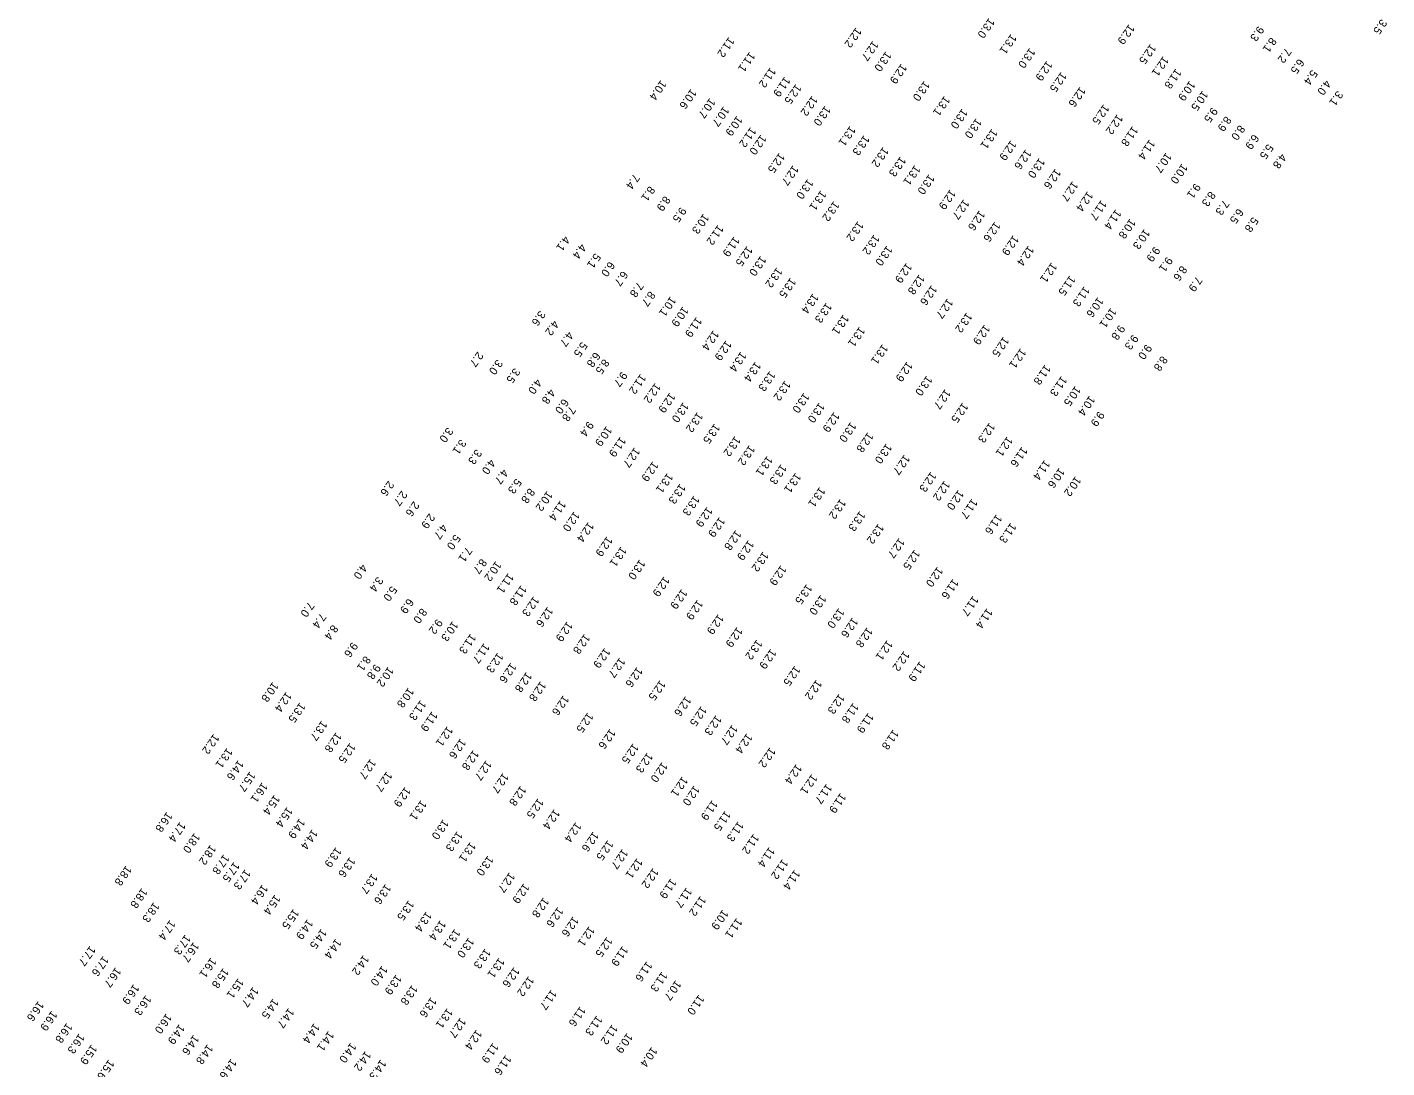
# Model space of a CAD drawing. Extents: x 815385 to 820851, y 582449 to 604245.
# Drawn here: x 818563 to 819412, y 587113 to 587763 of the extents above; entities that cross this region are included whole.
import ezdxf

# ---------------------------------------------------------------- set-up
doc = ezdxf.new("R2010")
doc.units = 0
doc.layers.add('V-TOPO-SOUN-021509', color=7, linetype='Continuous')

msp = doc.modelspace()

# ---------------------------------------------------------------- texts
at = {"layer": 'V-TOPO-SOUN-021509'}
for s, p in [('13.0 ', (819163.67, 587769.28)), ('3.5', (819408.79, 587768.65)), ('12.2 ', (819080.54, 587763.34)), ('12.9 ', (819251.12, 587765.37)), ('9.3', (819331.93, 587764.32)), ('11.2 ', (819001.1, 587757.36)), ('12.7 ', (819091.1, 587755.05)), ('13.1 ', (819177.41, 587759.3)), ('12.5 ', (819264.54, 587753.07)), ('8.1', (819339.75, 587757.22)), ('11.1 ', (819014.07, 587748.08)), ('13.0 ', (819099.21, 587748.44)), ('13.0 ', (819189.07, 587750.55)), ('12.1 ', (819272.52, 587745.38)), ('7.2', (819349.04, 587750.66)), ('6.5', (819357.13, 587743.9)), ('11.2 ', (819027.02, 587738.39)), ('12.9 ', (819108.87, 587740.75)), ('12.9 ', (819199.85, 587742.58)), ('12.5 ', (819208.76, 587735.56)), ('11.8 ', (819280.39, 587737.66)), ('5.4', (819365.43, 587736.98)), ('10.4 ', (818958.59, 587730.47)), ('11.9 ', (819036, 587732.64)), ('12.5 ', (819042.99, 587728.04)), ('13.0 ', (819123.2, 587729.98)), ('12.6 ', (819220.54, 587726.28)), ('10.9 ', (819289.01, 587730.06)), ('4.0', (819373.86, 587730.67)), ('10.6 ', (818977.42, 587725.03)), ('10.7 ', (818989.16, 587719.22)), ('12.2 ', (819053.14, 587720.69)), ('13.1 ', (819135.81, 587720.61)), ('10.5 ', (819297.1, 587723.93)), ('3.1', (819381.31, 587723.87)), ('10.7 ', (818997.84, 587714.08)), ('13.0 ', (819061.23, 587714.45)), ('13.0 ', (819146.88, 587712.65)), ('12.5 ', (819235.3, 587715.36)), ('12.2 ', (819243.84, 587709.12)), ('9.5', (819302.99, 587713.51)), ('10.9 ', (819006.15, 587708.19)), ('11.2 ', (819014.71, 587701.1)), ('13.1 ', (819076.81, 587701.82)), ('13.0 ', (819155.65, 587706.64)), ('11.8 ', (819253.37, 587701.71)), ('8.9', (819311.54, 587708)), ('8.0', (819320.07, 587702.48)), ('12.0 ', (819021.12, 587696.41)), ('13.3 ', (819085.55, 587696.06)), ('13.1 ', (819165.49, 587700.08)), ('12.9 ', (819177.26, 587692.87)), ('11.4 ', (819263.94, 587693.41)), ('6.9', (819328.83, 587696.71)), ('12.5 ', (819032.61, 587685.06)), ('13.2 ', (819097.49, 587688.67)), ('12.6 ', (819186.63, 587687.27)), ('10.7 ', (819274.33, 587685.21)), ('5.5', (819337.82, 587690.64)), ('4.8', (819346.06, 587684.73)), ('12.7 ', (819041.19, 587677.26)), ('13.3 ', (819108.26, 587682.75)), ('13.1 ', (819117.29, 587677.34)), ('13.0 ', (819195.11, 587681.87)), ('12.6 ', (819205.09, 587675.12)), ('10.0 ', (819284.26, 587678.31)), ('7.4', (818941.85, 587671.9)), ('13.0 ', (819050.41, 587668.74)), ('13.0 ', (819126.15, 587671.64)), ('12.7 ', (819215.88, 587667.34)), ('8.1', (818951.42, 587664.33)), ('8.9', (818961, 587658.18)), ('13.1 ', (819058.56, 587661.58)), ('12.9 ', (819139.4, 587662.18)), ('12.4 ', (819225.24, 587661)), ('9.1', (819292.35, 587666.1)), ('8.3', (819301.65, 587661.1)), ('9.5', (818970.97, 587651.19)), ('13.2 ', (819066.69, 587654.91)), ('12.7 ', (819147.83, 587656)), ('11.7 ', (819233.79, 587655.56)), ('11.4 ', (819242.84, 587649.74)), ('7.3', (819310.23, 587655.69)), ('6.5', (819319.14, 587650.38)), ('10.3 ', (818985.23, 587647.04)), ('13.2 ', (819081.77, 587642.33)), ('12.6 ', (819157.69, 587649.12)), ('12.6 ', (819167.32, 587642.06)), ('10.8 ', (819251.78, 587643.95)), ('5.8', (819328.44, 587645.05)), ('4.1', (818898.33, 587633.2)), ('11.2 ', (818994.33, 587640.06)), ('11.9 ', (819004.35, 587632.79)), ('13.2 ', (819091.82, 587633.97)), ('12.9 ', (819178.82, 587633.56)), ('10.3 ', (819260.73, 587637.47)), ('4.4', (818908.49, 587628.38)), ('12.5 ', (819012.46, 587626.8)), ('13.0 ', (819099.84, 587627.11)), ('12.4 ', (819188.26, 587627.02)), ('9.9', (819267.03, 587626.54)), ('5.1', (818917.54, 587622.42)), ('6.0', (818926.35, 587617.25)), ('13.0 ', (819020.98, 587620.7)), ('12.9 ', (819112.07, 587616.32)), ('12.1 ', (819202.72, 587616.52)), ('9.1', (819274.86, 587620.16)), ('6.7', (818934.53, 587611.35)), ('13.2 ', (819031.06, 587613.45)), ('13.5 ', (819039.57, 587607.03)), ('12.8 ', (819120.07, 587609.1)), ('11.5 ', (819214.16, 587608.46)), ('8.6', (819283.89, 587614.64)), ('7.9', (819293.34, 587607.89)), ('7.8', (818944.24, 587604.38)), ('8.7', (818951.61, 587598.69)), ('12.6 ', (819127.76, 587602.39)), ('11.3 ', (819223.17, 587601.66)), ('10.1 ', (818964.61, 587595.38)), ('13.4 ', (819053.65, 587597.24)), ('13.3 ', (819062, 587591.46)), ('12.7 ', (819137.74, 587594.1)), ('10.6 ', (819231.68, 587594.92)), ('3.6', (818882.95, 587586.56)), ('10.9 ', (818972.36, 587589.05)), ('11.9 ', (818980.81, 587582.45)), ('13.1 ', (819072.63, 587584.05)), ('13.2 ', (819149.67, 587585.31)), ('10.1 ', (819239.83, 587588.3)), ('4.2', (818891.43, 587580.5)), ('4.7', (818900.52, 587573.52)), ('12.4 ', (818991.42, 587574.17)), ('13.1 ', (819082.73, 587576.44)), ('12.9 ', (819160.84, 587577.76)), ('9.8', (819245.11, 587577.66)), ('5.5', (818909.19, 587567.05)), ('12.9 ', (818999.33, 587567.89)), ('13.1 ', (819097.09, 587565.54)), ('12.5 ', (819172.7, 587570.24)), ('9.3', (819253.44, 587571.57)), ('9.0', (819261.88, 587565.55)), ('2.7', (818844.14, 587560.88)), ('6.8', (818917.31, 587560.67)), ('8.5', (818922.84, 587556.36)), ('13.4 ', (819008.58, 587560.87)), ('12.1 ', (819183.4, 587562.97)), ('8.8', (819271.65, 587558.27)), ('3.0', (818856.25, 587556.03)), ('3.5', (818867.14, 587550.75)), ('9.7', (818934.16, 587548.47)), ('13.4 ', (819017.68, 587554.6)), ('13.3 ', (819026.71, 587548.74)), ('12.9 ', (819112.49, 587554.7)), ('11.8 ', (819198.68, 587552.74)), ('4.0', (818880.74, 587543.9)), ('11.2 ', (818945.93, 587546.93)), ('12.2 ', (818955.1, 587541.31)), ('13.2 ', (819036.17, 587542.77)), ('13.0 ', (819124.74, 587545.9)), ('11.3 ', (819208.92, 587545.61)), ('10.5 ', (819217.55, 587539.43)), ('4.8', (818889.19, 587537.74)), ('6.0', (818897.56, 587531.57)), ('12.9 ', (818964.18, 587535.22)), ('13.0 ', (819047.99, 587535.16)), ('12.7 ', (819136.26, 587537.46)), ('10.4 ', (819226.46, 587533.42)), ('7.8', (818901.89, 587526.86)), ('13.0 ', (818972.61, 587529.22)), ('13.2 ', (818981.46, 587523.06)), ('13.0 ', (819057.56, 587529.03)), ('12.9 ', (819066.83, 587523.11)), ('12.5 ', (819147.18, 587529.05)), ('9.9', (819232.22, 587523.7)), ('3.0', (818825.3, 587513.67)), ('9.4', (818913.11, 587517.43)), ('10.9 ', (818924.62, 587514.35)), ('13.5 ', (818992.12, 587515.93)), ('13.0 ', (819077.22, 587516.89)), ('12.3 ', (819163.94, 587516.54)), ('3.1', (818833.5, 587506.21)), ('11.9 ', (818933.31, 587507.66)), ('13.2 ', (819004.92, 587508.02)), ('12.8 ', (819087.95, 587510.49)), ('12.1 ', (819175.04, 587507.91)), ('3.3', (818843.24, 587499.99)), ('12.7 ', (818942.15, 587501.05)), ('13.2 ', (819013.93, 587502.45)), ('13.0 ', (819099.49, 587503.49)), ('12.7 ', (819110.75, 587496.5)), ('11.6 ', (819184.26, 587501.46)), ('4.0', (818851.8, 587493.78)), ('12.9 ', (818953.61, 587492.37)), ('13.1 ', (819025.08, 587495.74)), ('13.3 ', (819033.72, 587490.56)), ('11.4 ', (819198.38, 587493.21)), ('10.6 ', (819207.54, 587488.29)), ('2.6', (818788.39, 587480.27)), ('4.7', (818859.79, 587487.63)), ('5.3', (818868.07, 587481.66)), ('13.1 ', (818962.72, 587485.09)), ('13.1 ', (819042.79, 587485.17)), ('12.3 ', (819127.3, 587485.82)), ('12.2 ', (819135.81, 587480.29)), ('10.2 ', (819217.69, 587483.05)), ('2.7', (818796.64, 587474.07)), ('8.8', (818876.38, 587475.66)), ('10.2 ', (818887.55, 587473.84)), ('13.3 ', (818970.6, 587478.37)), ('13.1 ', (819057.85, 587476.29)), ('12.0 ', (819144.46, 587474.53)), ('2.6', (818804.18, 587467.46)), ('11.4 ', (818895.81, 587467.84)), ('13.3 ', (818979.34, 587470.95)), ('12.9 ', (818987.48, 587463.91)), ('13.2 ', (819070.76, 587468.88)), ('11.7 ', (819153.02, 587469.05)), ('2.9', (818813.93, 587459.87)), ('12.0 ', (818904.48, 587461.08)), ('12.4 ', (818913.29, 587454.45)), ('12.9 ', (818995.25, 587457.55)), ('13.3 ', (819082.92, 587461.29)), ('11.6 ', (819168.32, 587459.28)), ('11.3 ', (819177.22, 587453.96)), ('4.7', (818821.78, 587453.27)), ('5.0', (818829.92, 587446.74)), ('12.9 ', (818924.96, 587445.52)), ('12.8 ', (819005.41, 587449.38)), ('13.2 ', (819094.49, 587453.42)), ('7.1', (818837.14, 587438.98)), ('13.1 ', (818933.78, 587439.12)), ('12.9 ', (819013.32, 587443.1)), ('12.7 ', (819107.48, 587444.45)), ('12.5 ', (819117.12, 587437.21)), ('8.7', (818846.32, 587431.64)), ('10.2 ', (818855.47, 587430.06)), ('13.0 ', (818945.38, 587431.02)), ('13.2 ', (819022.49, 587436.01)), ('4.0', (818771.67, 587428.28)), ('3.4', (818781.59, 587420.4)), ('11.1 ', (818863.27, 587422.47)), ('12.9 ', (818960.61, 587420.44)), ('12.9 ', (819033.59, 587427.42)), ('12.0 ', (819131.42, 587426.49)), ('5.0', (818790.28, 587414.56)), ('11.8 ', (818871.29, 587414.96)), ('12.9 ', (818971.66, 587412.63)), ('13.5 ', (819049.69, 587415.68)), ('11.6 ', (819141.18, 587418.96)), ('7.0', (818738.52, 587404.63)), ('6.9', (818800.67, 587406.8)), ('12.3 ', (818879.12, 587408.04)), ('12.9 ', (818981.5, 587405.89)), ('13.0 ', (819058.51, 587408.98)), ('11.7 ', (819153.66, 587408.33)), ('7.4', (818745.91, 587397.61)), ('8.0', (818808.99, 587400.68)), ('12.6 ', (818887.83, 587401.46)), ('12.9 ', (818994.48, 587396.85)), ('13.0 ', (819069.79, 587400.67)), ('12.6 ', (819078.35, 587394.8)), ('11.4 ', (819162.43, 587400.59)), ('8.4', (818753.44, 587390.35)), ('9.2', (818818.69, 587393.98)), ('10.3 ', (818828.5, 587392.57)), ('12.9 ', (818900.09, 587392.35)), ('12.9 ', (819006.23, 587388.8)), ('12.8 ', (819087.52, 587388.68)), ('9.6', (818765.74, 587379.49)), ('11.3 ', (818839.73, 587384.72)), ('11.7 ', (818848.1, 587378.74)), ('12.8 ', (818910.91, 587384.58)), ('13.2 ', (819018.54, 587381.03)), ('12.1 ', (819100.03, 587380.67)), ('8.1', (818773.77, 587370.88)), ('12.3 ', (818856.69, 587372.87)), ('12.9 ', (818923.52, 587375.82)), ('12.7 ', (818932.9, 587369.78)), ('12.9 ', (819027.28, 587375.22)), ('12.2 ', (819110.56, 587373.9)), ('9.8', (818779.98, 587365.74)), ('10.2 ', (818788.26, 587364.09)), ('12.6 ', (818864.84, 587366.5)), ('12.8 ', (818874.58, 587360.68)), ('12.6 ', (818943.71, 587363.85)), ('12.5 ', (819042.32, 587364.67)), ('11.9 ', (819120.41, 587367.42)), ('10.8 ', (818716.15, 587354.61)), ('12.8 ', (818883.42, 587355)), ('12.5 ', (818958.06, 587355.62)), ('12.2 ', (819055.79, 587355.95)), ('12.4 ', (818724.55, 587348.36)), ('10.8 ', (818800.85, 587351.04)), ('12.6 ', (818897.73, 587346.24)), ('12.6 ', (818974.09, 587345.63)), ('12.3 ', (819070, 587347.12)), ('13.5 ', (818733.05, 587341.73)), ('11.3 ', (818808.42, 587343.18)), ('11.9 ', (818815.64, 587336.19)), ('12.5 ', (818912.94, 587335.48)), ('12.5 ', (818983.85, 587339.45)), ('11.8 ', (819078.78, 587341.44)), ('11.9 ', (819088.19, 587335.22)), ('13.7 ', (818746.7, 587330.44)), ('12.1 ', (818825.21, 587326.88)), ('12.3 ', (818993.05, 587333.76)), ('12.7 ', (819003.2, 587327.81)), ('12.2 ', (818679.2, 587322.09)), ('12.8 ', (818755.71, 587323.11)), ('12.6 ', (818833.39, 587319.21)), ('12.6 ', (818926.83, 587325.25)), ('12.4 ', (819012.31, 587322.45)), ('11.8 ', (819103.81, 587324.82)), ('13.1 ', (818687.56, 587313.33)), ('12.5 ', (818764.34, 587316.47)), ('12.8 ', (818841.43, 587312.05)), ('12.5 ', (818941.28, 587316.15)), ('12.3 ', (818950.15, 587310.42)), ('12.2 ', (819026.8, 587313.67)), ('14.6 ', (818694.56, 587305.77)), ('12.7 ', (818777.15, 587306.51)), ('12.7 ', (818849.48, 587305.61)), ('12.0 ', (818959.38, 587304.48)), ('12.4 ', (819043.25, 587303.25)), ('15.7 ', (818701.83, 587298.61)), ('12.7 ', (818787.28, 587298.62)), ('12.7 ', (818860.04, 587297.72)), ('12.1 ', (818972.01, 587295.48)), ('12.1 ', (819052.92, 587296.99)), ('16.1 ', (818709.48, 587291.76)), ('12.9 ', (818798.82, 587289.01)), ('12.8 ', (818871, 587289.71)), ('12.0 ', (818979.42, 587289.86)), ('11.7 ', (819062.13, 587290.95)), ('11.9 ', (819070.89, 587285.21)), ('15.4 ', (818717.14, 587284.05)), ('15.4 ', (818725.12, 587276.44)), ('13.1 ', (818808.72, 587280.7)), ('12.5 ', (818881.89, 587281.89)), ('11.9 ', (818990.74, 587280.74)), ('16.8 ', (818649.93, 587273.35)), ('17.4 ', (818658.17, 587267.16)), ('14.9 ', (818732.85, 587269.3)), ('13.0 ', (818822.61, 587268.71)), ('12.4 ', (818892.04, 587275.07)), ('11.5 ', (818998.83, 587274.11)), ('11.3 ', (819006.93, 587267.47)), ('18.0 ', (818667.19, 587260.26)), ('14.4 ', (818740.8, 587262.48)), ('13.3 ', (818831.38, 587261.27)), ('12.4 ', (818905.48, 587266.96)), ('12.6 ', (818916.34, 587261.1)), ('11.2 ', (819016.54, 587259.64)), ('18.2 ', (818677.2, 587252.89)), ('13.9 ', (818755.6, 587251.34)), ('13.1 ', (818839.54, 587254.61)), ('12.5 ', (818925.44, 587255.71)), ('12.7 ', (818934.61, 587250.26)), ('11.4 ', (819026.36, 587251.45)), ('17.8 ', (818685.51, 587246.91)), ('17.5 ', (818691.91, 587242.16)), ('13.6 ', (818764.22, 587245.12)), ('13.0 ', (818850.55, 587246.05)), ('12.1 ', (818943.73, 587244.46)), ('11.2 ', (819034.65, 587243.91)), ('18.8 ', (818624.48, 587239.87)), ('17.3 ', (818698.83, 587237.49)), ('13.7 ', (818778.14, 587234.82)), ('12.7 ', (818863.98, 587235.57)), ('12.2 ', (818953.75, 587238.29)), ('11.4 ', (819042.19, 587237.27)), ('18.8 ', (818634.32, 587225.82)), ('16.4 ', (818709.6, 587228.02)), ('13.6 ', (818786.58, 587228.32)), ('12.9 ', (818872.99, 587228.77)), ('11.9 ', (818964.86, 587231.8)), ('11.7 ', (818974.6, 587226.14)), ('18.3 ', (818641.79, 587216.99)), ('15.4 ', (818717.46, 587221.68)), ('13.5 ', (818800.99, 587218.15)), ('12.8 ', (818885.25, 587219.93)), ('11.2 ', (818983.41, 587220.87)), ('15.5 ', (818729.06, 587212.81)), ('13.4 ', (818812.03, 587211.16)), ('12.6 ', (818894.21, 587213.92)), ('12.6 ', (818903.79, 587208.05)), ('10.9 ', (818997.28, 587212.36)), ('17.4 ', (818651.85, 587205.87)), ('14.9 ', (818737.8, 587206.34)), ('14.5 ', (818746.43, 587200.39)), ('13.4 ', (818820.83, 587205.71)), ('13.1 ', (818829.82, 587200.28)), ('12.1 ', (818913.79, 587201.99)), ('11.1 ', (819005.97, 587207.07)), ('17.3 ', (818661.4, 587196.75)), ('16.7 ', (818666.62, 587192.1)), ('14.4 ', (818755.49, 587194.24)), ('13.0 ', (818838.49, 587194.87)), ('12.5 ', (818924.9, 587195.26)), ('17.7 ', (818601.92, 587189.71)), ('17.6 ', (818610.18, 587183.38)), ('16.1 ', (818677.42, 587182.36)), ('14.2 ', (818772.77, 587184.01)), ('13.3 ', (818848.84, 587188.05)), ('13.1 ', (818857.5, 587182.26)), ('11.9 ', (818934.71, 587189.62)), ('16.7 ', (818617.92, 587176.32)), ('15.8 ', (818685.2, 587175.86)), ('14.0 ', (818784.4, 587177.31)), ('12.6 ', (818866.84, 587176.4)), ('11.6 ', (818949.79, 587180.02)), ('11.3 ', (818959.28, 587173.62)), ('16.9 ', (818629.21, 587165.76)), ('15.1 ', (818694.5, 587169.48)), ('13.9 ', (818793.2, 587171.76)), ('13.8 ', (818803.18, 587165.31)), ('12.2 ', (818875.96, 587170.74)), ('10.7 ', (818967.85, 587168.22)), ('16.3 ', (818636.75, 587158.89)), ('14.7 ', (818703.75, 587164.04)), ('14.5 ', (818716.31, 587156.81)), ('13.6 ', (818814.99, 587157.57)), ('11.7 ', (818890.14, 587162.33)), ('11.0 ', (818982.3, 587159.17)), ('16.6 ', (818569.63, 587155.25)), ('16.9 ', (818578, 587149.19)), ('14.7 ', (818726.02, 587150.91)), ('13.1 ', (818825.14, 587150.76)), ('11.6 ', (818908.21, 587151.94)), ('16.8 ', (818587.42, 587141.6)), ('16.0 ', (818649.58, 587147.46)), ('14.9 ', (818657.68, 587140.8)), ('14.4 ', (818741.96, 587141.39)), ('12.7 ', (818833.33, 587144.84)), ('11.3 ', (818918.57, 587146.19)), ('11.2 ', (818928.24, 587140.64)), ('16.3 ', (818595.1, 587134.93)), ('14.6 ', (818666.63, 587134.13)), ('14.1 ', (818750.9, 587136.51)), ('12.4 ', (818843.35, 587137.32)), ('10.9 ', (818937.52, 587135.26)), ('15.9 ', (818602.86, 587128.1)), ('14.8 ', (818675.34, 587128.24)), ('14.0 ', (818764.84, 587129.24)), ('14.2 ', (818774.01, 587124.06)), ('11.9 ', (818853.7, 587129.1)), ('10.4 ', (818952.9, 587126.57)), ('15.6 ', (818613.61, 587118.71)), ('14.6 ', (818690.05, 587119.19)), ('14.3 ', (818783.55, 587118.74)), ('11.6 ', (818861.69, 587121.55))]:
    msp.add_text(s, height=5, rotation=234.911, dxfattribs=at).set_placement(p)

doc.saveas('drawing.dxf')
